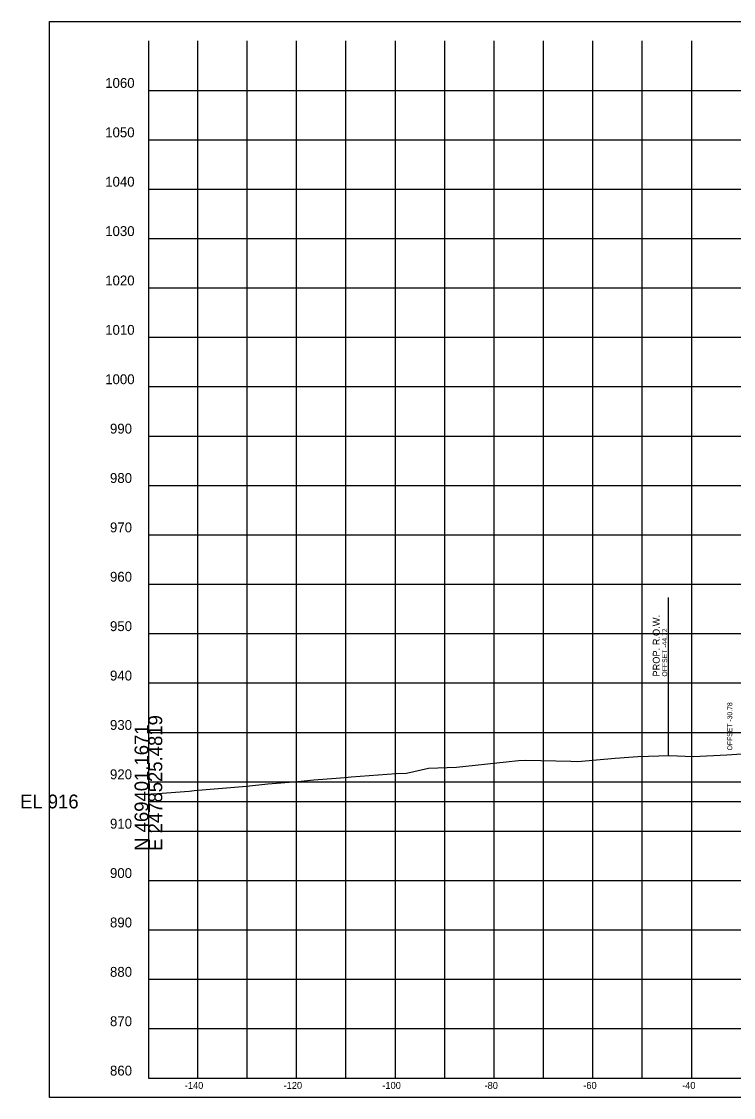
# Model space of a CAD drawing. Extents: x -26 to 2478923, y -10 to 469990.
# Drawn here: x -25.7 to 118.5, y 8940.1 to 9157.9 of the extents above; entities that cross this region are included whole.
import ezdxf

# ---------------------------------------------------------------- set-up
doc = ezdxf.new("R2010")
doc.units = 0
for name, color, linetype in [('DESIGN - ROW - Right-of-Way and Easement Labels', 7, 'Continuous'), ('DESIGN - ROW - Right-of-Way Linework', 7, 'Continuous'), ('DESIGN - SHEET - Corner Text', 7, 'Continuous'), ('DESIGN - SHEET - Light Grid', 7, 'Continuous'), ('DESIGN - SHEET - Linework', 7, 'Continuous'), ('DESIGN - SHEET - Plot Shape', 7, 'Continuous'), ('DESIGN - TYPICAL - Slope Tie Text', 7, 'Continuous'), ('SURVEY - GROUND - Top of Ground', 7, 'Continuous')]:
    doc.layers.add(name, color=color, linetype=linetype)

msp = doc.modelspace()

# ---------------------------------------------------------------- linework, layer by layer
at = {"layer": 'DESIGN - ROW - Right-of-Way Linework'}
msp.add_line((105.28, 9009.29), (105.28, 9041.29), dxfattribs=at)
at = {"layer": 'DESIGN - SHEET - Light Grid'}
msp.add_line((0, 9000), (150, 9000), dxfattribs=at)
at = {"layer": 'DESIGN - SHEET - Linework'}
for p, q in [((10, 8944), (10, 9154)), ((10, 8944), (10, 9154)), ((10, 8944), (10, 9154)), ((10, 8944), (10, 9154)), ((20, 8944), (20, 9154)), ((20, 8944), (20, 9154)), ((20, 8944), (20, 9154)), ((20, 8944), (20, 9154)), ((30, 8944), (30, 9154)), ((30, 8944), (30, 9154)), ((30, 8944), (30, 9154)), ((30, 8944), (30, 9154)), ((40, 8944), (40, 9154)), ((40, 8944), (40, 9154)), ((40, 8944), (40, 9154)), ((40, 8944), (40, 9154)), ((50, 8944), (50, 9154)), ((50, 8944), (50, 9154)), ((50, 8944), (50, 9154)), ((50, 8944), (50, 9154)), ((60, 8944), (60, 9154)), ((60, 8944), (60, 9154)), ((60, 8944), (60, 9154)), ((60, 8944), (60, 9154)), ((70, 8944), (70, 9154)), ((70, 8944), (70, 9154)), ((70, 8944), (70, 9154)), ((70, 8944), (70, 9154)), ((80, 8944), (80, 9154)), ((80, 8944), (80, 9154)), ((80, 8944), (80, 9154)), ((80, 8944), (80, 9154)), ((90, 8944), (90, 9154)), ((90, 8944), (90, 9154)), ((90, 8944), (90, 9154)), ((90, 8944), (90, 9154)), ((100, 8944), (100, 9154)), ((100, 8944), (100, 9154)), ((100, 8944), (100, 9154)), ((100, 8944), (100, 9154)), ((110, 8944), (110, 9154)), ((110, 8944), (110, 9154)), ((110, 8944), (110, 9154)), ((110, 8944), (110, 9154)), ((0, 9144), (300, 9144)), ((0, 9144), (300, 9144)), ((0, 9144), (300, 9144)), ((0, 9144), (300, 9144)), ((0, 9134), (300, 9134)), ((0, 9134), (300, 9134)), ((0, 9134), (300, 9134)), ((0, 9134), (300, 9134)), ((0, 9124), (300, 9124)), ((0, 9124), (300, 9124)), ((0, 9124), (300, 9124)), ((0, 9124), (300, 9124)), ((0, 9114), (300, 9114)), ((0, 9114), (300, 9114)), ((0, 9114), (300, 9114)), ((0, 9114), (300, 9114)), ((0, 9104), (300, 9104)), ((0, 9104), (300, 9104)), ((0, 9104), (300, 9104)), ((0, 9104), (300, 9104)), ((0, 9094), (300, 9094)), ((0, 9094), (300, 9094)), ((0, 9094), (300, 9094)), ((0, 9094), (300, 9094)), ((0, 9084), (300, 9084)), ((0, 9084), (300, 9084)), ((0, 9084), (300, 9084)), ((0, 9084), (300, 9084)), ((0, 9074), (300, 9074)), ((0, 9074), (300, 9074)), ((0, 9074), (300, 9074)), ((0, 9074), (300, 9074)), ((0, 9064), (300, 9064)), ((0, 9064), (300, 9064)), ((0, 9064), (300, 9064)), ((0, 9064), (300, 9064)), ((0, 9054), (300, 9054)), ((0, 9054), (300, 9054)), ((0, 9054), (300, 9054)), ((0, 9054), (300, 9054)), ((0, 9044), (300, 9044)), ((0, 9044), (300, 9044)), ((0, 9044), (300, 9044)), ((0, 9044), (300, 9044)), ((0, 9034), (300, 9034)), ((0, 9034), (300, 9034)), ((0, 9034), (300, 9034)), ((0, 9034), (300, 9034)), ((0, 9024), (300, 9024)), ((0, 9024), (300, 9024)), ((0, 9024), (300, 9024)), ((0, 9024), (300, 9024)), ((0, 9014), (300, 9014)), ((0, 9014), (300, 9014)), ((0, 9014), (300, 9014)), ((0, 9014), (300, 9014)), ((0, 9004), (300, 9004)), ((0, 9004), (300, 9004)), ((0, 9004), (300, 9004)), ((0, 9004), (300, 9004)), ((0, 8994), (300, 8994)), ((0, 8994), (300, 8994)), ((0, 8994), (300, 8994)), ((0, 8994), (300, 8994)), ((0, 8984), (300, 8984)), ((0, 8984), (300, 8984)), ((0, 8984), (300, 8984)), ((0, 8984), (300, 8984)), ((0, 8974), (300, 8974)), ((0, 8974), (300, 8974)), ((0, 8974), (300, 8974)), ((0, 8974), (300, 8974)), ((0, 8964), (300, 8964)), ((0, 8964), (300, 8964)), ((0, 8964), (300, 8964)), ((0, 8964), (300, 8964)), ((0, 8954), (300, 8954)), ((0, 8954), (300, 8954)), ((0, 8954), (300, 8954)), ((0, 8954), (300, 8954))]:
    msp.add_line(p, q, dxfattribs=at)
msp.add_lwpolyline([(0, 9154), (0, 8944), (300, 8944), (300, 9154)], dxfattribs=at)
msp.add_lwpolyline([(0, 9154), (0, 8944), (300, 8944), (300, 9154)], dxfattribs=at)
msp.add_lwpolyline([(0, 9154), (0, 8944), (300, 8944), (300, 9154)], dxfattribs=at)
msp.add_lwpolyline([(0, 9154), (0, 8944), (300, 8944), (300, 9154)], dxfattribs=at)
at = {"layer": 'DESIGN - SHEET - Plot Shape'}
msp.add_lwpolyline([(-20, 9157.94), (320, 9157.94), (320, 8940.06), (-20, 8940.06)], close=True, dxfattribs=at)
msp.add_lwpolyline([(-20, 9157.94), (320, 9157.94), (320, 8940.06), (-20, 8940.06)], close=True, dxfattribs=at)
msp.add_lwpolyline([(-20, 9157.94), (320, 9157.94), (320, 8940.06), (-20, 8940.06)], close=True, dxfattribs=at)
msp.add_lwpolyline([(-20, 9157.94), (320, 9157.94), (320, 8940.06), (-20, 8940.06)], close=True, dxfattribs=at)
at = {"layer": 'SURVEY - GROUND - Top of Ground'}
msp.add_lwpolyline([(0, 9001.45), (8.25, 9002.12), (8.76, 9002.17), (9.26, 9002.22), (19.83, 9003.07), (24.2, 9003.58), (30.28, 9004.06), (33.5, 9004.41), (38.91, 9004.82), (40.45, 9004.94), (41.05, 9004.98), (50.14, 9005.66), (52.23, 9005.76), (56.7, 9006.73), (62.39, 9006.95), (72.41, 9008), (74.93, 9008.31), (76.42, 9008.39), (85.54, 9008.13), (86.94, 9008.08), (94.5, 9008.8), (99.09, 9009.14), (105.52, 9009.29), (110.3, 9009.13), (117.1, 9009.45), (125.24, 9009.96)], dxfattribs=at)

# ---------------------------------------------------------------- texts
at = {"layer": 'DESIGN - ROW - Right-of-Way and Easement Labels'}
for s, height, p in [('PROP. R.O.W.', 1.4, (103.53, 9025.29)), ('OFFSET -44.72', 1, (105.03, 9025.29))]:
    msp.add_text(s, height=height, rotation=90, dxfattribs=at).set_placement(p)
at = {"layer": 'DESIGN - SHEET - Corner Text'}
for s, height, p in [('1060', 2, (-8.75, 9144.5)), ('1060', 2, (-8.75, 9144.5)), ('1060', 2, (-8.75, 9144.5)), ('1060', 2, (-8.75, 9144.5)), ('1050', 2, (-8.75, 9134.5)), ('1050', 2, (-8.75, 9134.5)), ('1050', 2, (-8.75, 9134.5)), ('1050', 2, (-8.75, 9134.5)), ('1040', 2, (-8.75, 9124.5)), ('1040', 2, (-8.75, 9124.5)), ('1040', 2, (-8.75, 9124.5)), ('1040', 2, (-8.75, 9124.5)), ('1030', 2, (-8.75, 9114.5)), ('1030', 2, (-8.75, 9114.5)), ('1030', 2, (-8.75, 9114.5)), ('1030', 2, (-8.75, 9114.5)), ('1020', 2, (-8.75, 9104.5)), ('1020', 2, (-8.75, 9104.5)), ('1020', 2, (-8.75, 9104.5)), ('1020', 2, (-8.75, 9104.5)), ('1010', 2, (-8.75, 9094.5)), ('1010', 2, (-8.75, 9094.5)), ('1010', 2, (-8.75, 9094.5)), ('1010', 2, (-8.75, 9094.5)), ('1000', 2, (-8.75, 9084.5)), ('1000', 2, (-8.75, 9084.5)), ('1000', 2, (-8.75, 9084.5)), ('1000', 2, (-8.75, 9084.5)), ('990', 2, (-7.78, 9074.5)), ('990', 2, (-7.78, 9074.5)), ('990', 2, (-7.78, 9074.5)), ('990', 2, (-7.78, 9074.5)), ('980', 2, (-7.78, 9064.5)), ('980', 2, (-7.78, 9064.5)), ('980', 2, (-7.78, 9064.5)), ('980', 2, (-7.78, 9064.5)), ('970', 2, (-7.78, 9054.5)), ('970', 2, (-7.78, 9054.5)), ('970', 2, (-7.78, 9054.5)), ('970', 2, (-7.78, 9054.5)), ('960', 2, (-7.78, 9044.5)), ('960', 2, (-7.78, 9044.5)), ('960', 2, (-7.78, 9044.5)), ('960', 2, (-7.78, 9044.5)), ('950', 2, (-7.78, 9034.5)), ('950', 2, (-7.78, 9034.5)), ('950', 2, (-7.78, 9034.5)), ('950', 2, (-7.78, 9034.5)), ('940', 2, (-7.78, 9024.5)), ('940', 2, (-7.78, 9024.5)), ('940', 2, (-7.78, 9024.5)), ('940', 2, (-7.78, 9024.5)), ('930', 2, (-7.78, 9014.5)), ('930', 2, (-7.78, 9014.5)), ('930', 2, (-7.78, 9014.5)), ('930', 2, (-7.78, 9014.5)), ('920', 2, (-7.78, 9004.5)), ('920', 2, (-7.78, 9004.5)), ('920', 2, (-7.78, 9004.5)), ('920', 2, (-7.78, 9004.5)), ('910', 2, (-7.78, 8994.5)), ('910', 2, (-7.78, 8994.5)), ('910', 2, (-7.78, 8994.5)), ('910', 2, (-7.78, 8994.5)), ('900', 2, (-7.78, 8984.5)), ('900', 2, (-7.78, 8984.5)), ('900', 2, (-7.78, 8984.5)), ('900', 2, (-7.78, 8984.5)), ('890', 2, (-7.78, 8974.5)), ('890', 2, (-7.78, 8974.5)), ('890', 2, (-7.78, 8974.5)), ('890', 2, (-7.78, 8974.5)), ('880', 2, (-7.78, 8964.5)), ('880', 2, (-7.78, 8964.5)), ('880', 2, (-7.78, 8964.5)), ('880', 2, (-7.78, 8964.5)), ('870', 2, (-7.78, 8954.5)), ('870', 2, (-7.78, 8954.5)), ('870', 2, (-7.78, 8954.5)), ('870', 2, (-7.78, 8954.5)), ('860', 2, (-7.78, 8944.5)), ('860', 2, (-7.78, 8944.5)), ('860', 2, (-7.78, 8944.5)), ('860', 2, (-7.78, 8944.5)), ('-140', 1.4, (7.37, 8941.8)), ('-140', 1.4, (7.37, 8941.8)), ('-140', 1.4, (7.37, 8941.8)), ('-140', 1.4, (7.37, 8941.8)), ('-120', 1.4, (27.37, 8941.8)), ('-120', 1.4, (27.37, 8941.8)), ('-120', 1.4, (27.37, 8941.8)), ('-120', 1.4, (27.37, 8941.8)), ('-100', 1.4, (47.37, 8941.8)), ('-100', 1.4, (47.37, 8941.8)), ('-100', 1.4, (47.37, 8941.8)), ('-100', 1.4, (47.37, 8941.8)), ('-80', 1.4, (68.06, 8941.8)), ('-80', 1.4, (68.06, 8941.8)), ('-80', 1.4, (68.06, 8941.8)), ('-80', 1.4, (68.06, 8941.8)), ('-60', 1.4, (88.06, 8941.8)), ('-60', 1.4, (88.06, 8941.8)), ('-60', 1.4, (88.06, 8941.8)), ('-60', 1.4, (88.06, 8941.8)), ('-40', 1.4, (108.06, 8941.8)), ('-40', 1.4, (108.06, 8941.8)), ('-40', 1.4, (108.06, 8941.8)), ('-40', 1.4, (108.06, 8941.8))]:
    msp.add_text(s, height=height, dxfattribs=at).set_placement(p)
at = {"layer": 'DESIGN - SHEET - Light Grid'}
for s, p in [('E 2478525.4819', (2.8, 8990)), ('N 469401.1671', (0, 8990))]:
    msp.add_text(s, height=2.8, rotation=90, dxfattribs=at).set_placement(p)
msp.add_text('EL 916', height=2.8, dxfattribs=at).set_placement((-26, 8998.6))
at = {"layer": 'DESIGN - TYPICAL - Slope Tie Text'}
msp.add_text('OFFSET -30.78', height=1, rotation=90, dxfattribs=at).set_placement((118.22, 9010.34))

doc.saveas('drawing.dxf')
